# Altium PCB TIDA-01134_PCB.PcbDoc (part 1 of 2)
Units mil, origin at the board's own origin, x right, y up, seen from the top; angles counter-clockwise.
Board outline 4724.41 x 2283.46 mil, 2 copper layers (Top Layer, Bottom Layer), stack 62 mil thick; 90 components, 33 nets, 177 pads, 316 vias.
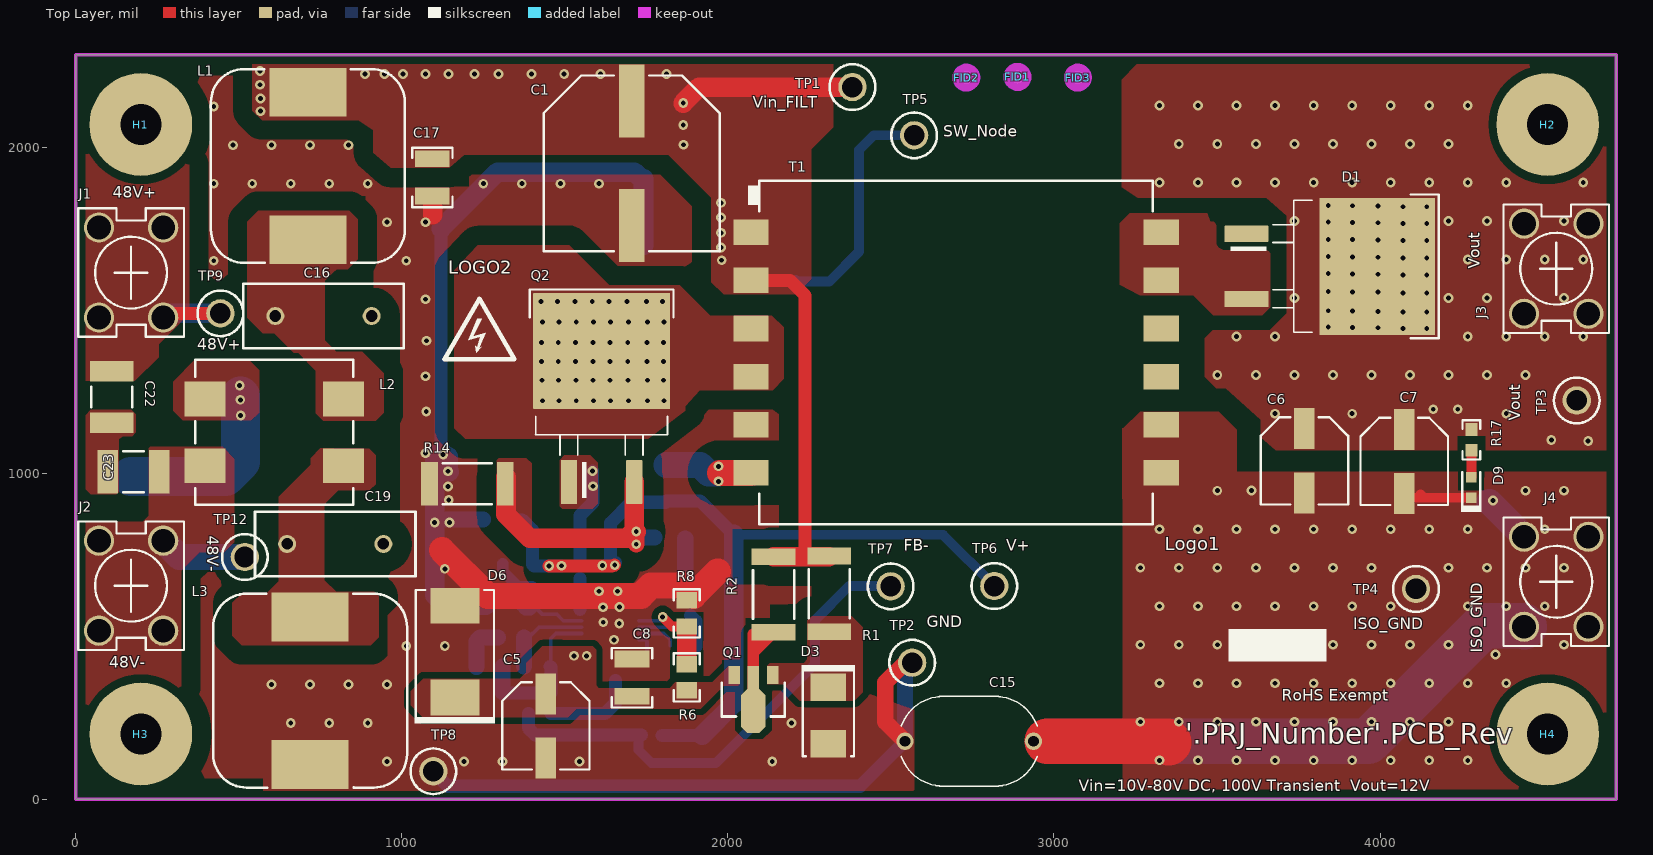
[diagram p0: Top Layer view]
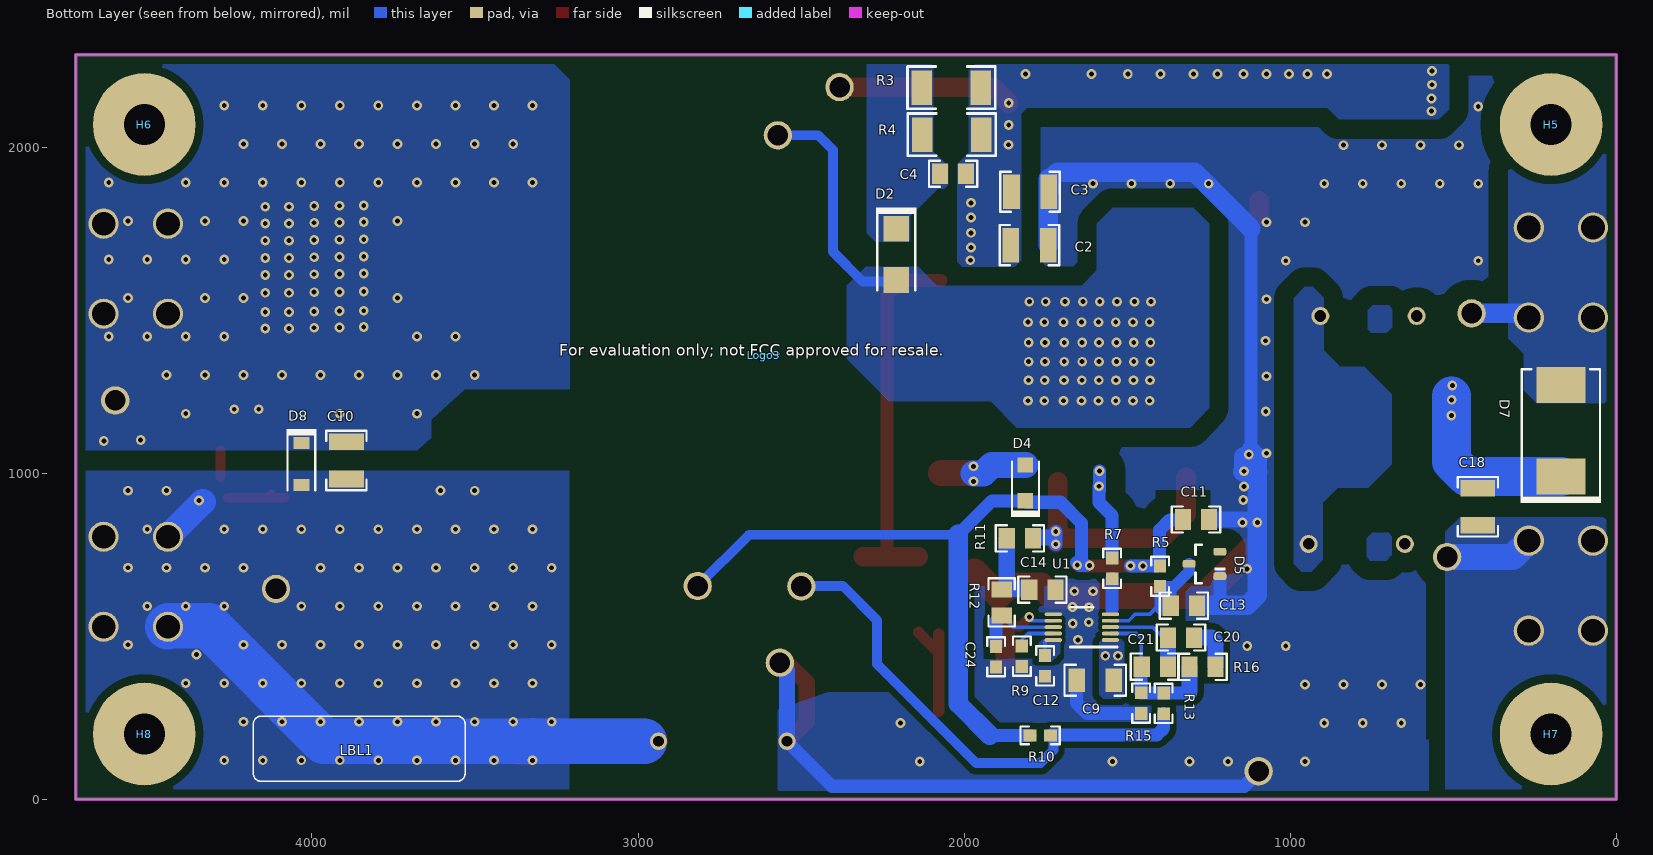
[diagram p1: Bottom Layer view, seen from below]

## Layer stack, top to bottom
Top Solder: solder mask 0.4, Solder Resist, Dk 3.5
Top Layer: signal copper 1.4
Dielectric1: core 59.2, FR-4, Dk 4.8
Bottom Layer: signal copper 1.4
Bottom Solder: solder mask 0.4, Solder Resist, Dk 3.5

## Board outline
0,0 4724.41,0 4724.41,2283.46 0,2283.46

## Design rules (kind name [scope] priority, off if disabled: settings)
AcuteAngle [All] p1: minimum=4.50000000000000E+0001 checktracksonly=FALSE
AssemblyTestPointUsage [All] p1: valid=2
BoardOutlineClearance BoardOutlineClearance_MountingHoles [OnCopper and InComponentClass('Mounting Holes')] p1: gap=21
BoardOutlineClearance BoardOutlineClearance_Poly [OnCopper and IsPoly] p2: gap=25
BoardOutlineClearance [OnCopper and Not InComponentClass('Logo') and not InComponentClass('FiducialMark') and not InRegion(1000,500,4000,800) and not InPoly] p3: gap=0
Clearance Clearance_PolyGND_LV [InNamedPolygon('BOTTOM_LAYER_GND_LV')or InNamedPolygon('TOP_LAYER_GND_LV')] p1: gap=20
Clearance Clearance_PolyGND_Big [InNamedPolygon('TOP_LAYER_GND_P064') Or InNamedPolygon ('BOTTOM_LAYER_GND_P066')or InNamedPolygon('BOTTOM_LAYER_GND_LV')] p2: gap=60
Clearance Clearance_Poly_U1 [InPolygon vs InNet('FB') OR InNet('COMP') OR InNet('VCC') OR InNet('OUT') OR InNet('CS') or InNet('UVLO') or InNet('RT/SYNC')or InNet('SS')] p3: gap=12
Clearance Clearance_Poly [InPolygon] p4: gap=25
Clearance Clearance_U1 [(InNet('VIN') OR InNet('FB') OR InNet('COMP') OR InNet('VCC') OR InNet('OUT') OR InNet('CS') or InNet('UVLO') or InNet('RT/SYNC')or InNet('SS'))or ( InNet('GND') ) vs (InNet('VIN') OR InNet('FB') OR InNet('COMP') OR InNet('VCC') OR InNet('OUT') OR InNet('CS') or InNet('UVLO') or InNet('RT/SYNC')or InNet('SS'))  or ( InNet('GND') and InComponent('U1'))] p5: gap=7.8
Clearance Clearance_Keepouts [((IsTrack Or IsArc) And Not InPoly) And IsFree and IsKeepOut vs ((IsTrack Or IsArc) And Not InPoly) And IsFree and IsKeepOut] p6: gap=0
Clearance [All] p7: gap=12
ComponentClearance ComponentClearance_MountingHoles_FiducialMarks [InComponentClass('Mounting Holes') vs InComponentClass('FiducialMark')] p1: gap=50 collisioncheckmode=3 verticalgap=10 showdistances=FALSE
ComponentClearance ComponentClearance_Shunt [InComponentClass('Header') vs InComponentClass('Shunt')] p2: gap=0 collisioncheckmode=3 verticalgap=0 showdistances=FALSE
ComponentClearance ComponentClearance_Logo [InComponentClass('Logo')] p3: gap=50 collisioncheckmode=3 verticalgap=10 showdistances=FALSE
ComponentClearance ComponentClearance_ScrewToNut [(HasFootprint('NY PMS 440 0025 PH')) vs (HasFootprint('Keystone_1902C'))] p4: gap=5 collisioncheckmode=3 verticalgap=10 showdistances=FALSE
ComponentClearance ComponentClearance_MountingHoles [InComponentClass('Mounting Holes')] p5: gap=78.74 collisioncheckmode=3 verticalgap=100000 showdistances=FALSE
ComponentClearance ComponentClearance_SmallPassives [HasFootprint('0201*') or HasFootprint('0402*') or HasFootprint('0508') or HasFootprint('0603*') or HasFootprint('0612') or HasFootprint('0805*') or HasFootprint('0815*') or HasFootprint('0830*') or HasFootprint('1206*') or HasFootprint('1210*') or HasFootprint('1808*') or HasFootprint('1812*') or HasFootprint('1825*') or HasFootprint('2010*') or HasFootprint('2220*') or HasFootprint('2225*') or HasFootprint('2512*') or HasFootprint('2728*') or HasFootprint('3518*') vs HasFootprint('0201*') or HasFootprint('0402*') or HasFootprint('0508') or HasFootprint('0603*') or HasFootprint('0612') or HasFootprint('0805*') or HasFootprint('0815*') or HasFootprint('0830*') or HasFootprint('1206*') or HasFootprint('1210*') or HasFootprint('1808*') or HasFootprint('1812*') or HasFootprint('1825*') or HasFootprint('2010*') or HasFootprint('2220*') or HasFootprint('2225*') or HasFootprint('2512*') or HasFootprint('2728*') or HasFootprint('3518*')] p6: gap=14.96 collisioncheckmode=3 verticalgap=10 showdistances=FALSE
ComponentClearance ComponentClearance_THtoSMT [IsThruComponent vs IsSMTComponent] p7: gap=20 collisioncheckmode=3 verticalgap=20 showdistances=FALSE
ComponentClearance ComponentClearance_THtoTH [IsThruComponent vs IsThruComponent] p8: gap=30 collisioncheckmode=3 verticalgap=20 showdistances=FALSE
ComponentClearance [All] p9: gap=30 collisioncheckmode=3 verticalgap=10 showdistances=FALSE
DiffPairsRouting [All] p1: maxlimit=100 minlimit=10 mostfreqgap=10 toplayer_minwidth=15 toplayer_maxwidth=15 toplayer_prefwidth=15 bottomlayer_minwidth=15 bottomlayer_maxwidth=15 bottomlayer_prefwidth=15 maxuncoupledlength=1000
FabricationTestPointUsage TestPointUsage [All] p1: valid=2 allowmultiple=FALSE
FabricationTestpoint Testpoint [All] p1: side=3 testpointundercomponent=TRUE minsize=40 maxsize=100 preferedsize=60 minholesize=0 maxholesize=40 preferedholesize=32 testpointgrid=1 allowsidetop=TRUE allowsidebottom=TRUE usegrid=TRUE gridtolerance=0.01
FanoutControl Fanout_LCC [IsLCC] p1: bgadir=Out bgaviamode=Centered fanoutstyle=Auto fanoutdirection=Alternating viagrid=1 // Fanout_LCC (Default Rule)
FanoutControl Fanout_BGA [IsBGA] p2: bgadir=Out bgaviamode=Centered fanoutstyle=Auto fanoutdirection=Alternating viagrid=1 // Fanout_BGA (Default Rule)
FanoutControl Fanout_Default [All] p4: bgadir=Out bgaviamode=Centered fanoutstyle=Auto fanoutdirection=Alternating viagrid=1 // Fanout_Default (Default Rule)
FanoutControl Fanout_Small [(CompPinCount < 5)] p5: bgadir=Out bgaviamode=Centered fanoutstyle=Auto fanoutdirection=OutThenIn viagrid=1 // Fanout_Small (Default Rule)
HoleSize [All] p1: absolutevalues=TRUE maxlimit=251 minlimit=7.87 maxpercent=80.000 minpercent=20.000
MinimumAnnularRing MinimumAnnularRing_ThermalPadVias [IsVia and InAnyComponent] p1: minimumring=5.91
MinimumAnnularRing [All] p2: minimumring=7
MinimumSolderMaskSliver MinimumSolderMaskSliver_Logo [InComponentClass('Logo') vs InComponentClass('Logo')] p1: minsoldermaskwidth=0.7
MinimumSolderMaskSliver [All] p2: minsoldermaskwidth=2
PlaneConnect [All] p1: planeconnectstyle=Direct reliefexpansion=10 reliefentries=4 reliefconductorwidth=10 reliefairgap=10
PolygonConnect [All] p1: connectstyle=Direct reliefconductorwidth=10 reliefentries=4 polygonreliefangle="90 Angle" airgapwidth=10
RoutingVias ThermalPadVias [IsVia and InAnyComponent] p1: holewidth=7.87 width=19.68 viastyle="Through Hole" minholewidth=7.87 minwidth=19.68 maxholewidth=12.99 maxwidth=23.62
RoutingVias [All] p2: holewidth=16 width=34 viastyle="Through Hole" minholewidth=7.87 minwidth=26 maxholewidth=40 maxwidth=65
SilkToBoardRegionClearance [Not ((IsComment or IsDesignator) And (Hide <> 'False')) and not InRegion(1000,500,4000,800)] p1:
SilkToSilkClearance SilkToSilkClearance_Pb-FreeLogo [(HasFootprint('Pb-Free_Overlay_Medium') OR HasFootprint('Pb-Free_Overlay_Small')) vs (HasFootprint('Pb-Free_Overlay_Medium') OR HasFootprint('Pb-Free_Overlay_Small'))] p1: silktosilkclearance=0
SilkToSilkClearance [All] p2: silktosilkclearance=4
SilkToSolderMaskClearance SilkToComponentPadClearance [IsPad and InAnycomponent] p1: minsilkscreentomaskgap=0 clearancetoexposedcopper=TRUE
SilkToSolderMaskClearance "Silk to Solder Mask Opening" [All] p2: minsilkscreentomaskgap=0 clearancetoexposedcopper=FALSE
SolderMaskExpansion [All] p1: expansion=2
Width [All] p1: maxlimit=400 minlimit=6 preferedwidth=10 checkconnectedcopper=TRUE
15 further rules are at their usual default settings.

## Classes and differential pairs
component class Label: LBL1
component class AssemblyNote: ZZ1 ZZ2 ZZ3 ZZ4
component class FiducialMark: FID1 FID2 FID3
component class TIDA-01134_Hardware: FID1 FID2 FID3 H1 H2 H3 H4 H5 H6 H7 H8 LBL1 Logo1 LOGO2 Logo3 ZZ1 ZZ2 ZZ3 ZZ4
component class "Mounting Holes": H1 H2 H3 H4
component class TIDA-01134_FlyBack_Converter: C1 C2 C3 C4 C5 C6 C7 C8 C9 C10 C11 C12 C13 C14 C15 C20 C21 C24 D1 D2 D3 D4 D5 D6 D8 D9 J3 J4 Q1 Q2 R1 R2 R3 R4 R5 R6 R7 R8 R9 R10 R11 R12 R13 R14 R15 R16 R17 T1 TP2 TP3 TP4 TP5 TP6 TP7 TP8 U1
component class TIDA-01134_Protection_EMI_Filter: C16 C17 C18 C19 C22 C23 D7 J1 J2 L1 L2 L3 TP1 TP9 TP12

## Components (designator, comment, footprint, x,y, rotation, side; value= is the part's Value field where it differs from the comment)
C1 "EEV-FK2A470Q" SM_RADIAL_H13 1705,1950 r270 top
C2 "GRM32DC72A475KE01L" 1210_220 1799.57,1699 r180 bottom
C3 "GRM32DC72A475KE01L" 1210_220 1797.89,1863 r180 bottom
C4 "CGA4J2X7R2A104K125AA" 0805_HV 2034,1918 r0 bottom
C5 "EEE-FK1K4R7P" SM_RADIAL_D 1442,225 r270 top
C6 "EEE-FK1E101XP" SM_RADIAL_D8 3768,1038 r270 top
C7 "EEE-FK1E101XP" SM_RADIAL_D8 4074,1036 r270 top
C8 "GRM32DC72A475KE01L" 1210_220 1706,373 r90 top
C9 "GRM319R72A104KA01D" 1206 1598,365 r0 bottom
C10 "GRM32ER71E226KE15L" 1210_270 3894,1039 r270 bottom
C11 "GRM216R61E105KA12D" 0805_HV 1289,858 r180 bottom
C12 "GRM188R71H104KA93D" 0603 1752,409 r270 bottom
C13 "GRM216R61E105KA12D" 0805_HV 1326,594 r180 bottom
C14 "GCM2165C1H102JA16D" 0805_HV 1760,643 r180 bottom
C15 "DE1E3KX222MA4BL01" CAPRD1000W60D900H1200 2740,178 r180 top
C16 "VY2472M49Y5US63V7" VY2_1250x500x1650 760,1482 r0 top
C17 "GRM32DC72A475KE01L" 1210_220 1094,1907 r270 top
C18 "GRM32DC72A475KE01L" 1210_220 425,897 r270 bottom
C19 "VY2472M49Y5US63V7" VY2_1250x500x1650 796,783 r180 top
C20 "GRM219R71H333KA01D" 0805_HV 1335,496 r180 bottom
C21 "GRM2165C1H821JA01D" 0805_HV 1415,407 r0 bottom
C22 "VJ1812Y103KXEAT5Z" 1812 111,1234 r270 top
C23 "VJ1812Y103KXEAT5Z" 1812 177,1004 r0 top
C24 "GRM1885C1H100JA01D" 0603 1902,437 r270 bottom
D1 "STPS8H100G-TR" DDPAK 3836,1634 r0 top
D2 "STPS1150A" SMA 2208,1671 r270 bottom
D3 "1SMB5942BT3G" SMB 2308,257 r270 top
D4 "PMEG10010ELRX" SOD-123W 1812,970 r90 bottom
D5 "MMBZ5244BLT1G" SOT-23 1263,722 r0 bottom
D6 "SMCJ54A" SMC 1163,453 r90 top
D7 "B3100-13-F" SMC 170,1130 r90 bottom
D8 "MMSZ5246B-7-F" SOD-123 4031.95,1028 r270 bottom
D9 "150060GS75000" WL-SMCW_GREEN 4279.22,956 r90 top
FID1 "Fiducial" Fiducial10-20 2888,2215 r0 top
FID2 "Fiducial" Fiducial10-20 2731,2213 r0 top
FID3 "Fiducial" Fiducial10-20 3073,2213 r0 top
H1 "NY PMS 440 0025 PH" "NY PMS 440 0025 PH" 200,2068.9 r0 top locked
H2 "NY PMS 440 0025 PH" "NY PMS 440 0025 PH" 4513.78,2068.9 r0 top locked
H3 "NY PMS 440 0025 PH" "NY PMS 440 0025 PH" 200,200 r0 top locked
H4 "NY PMS 440 0025 PH" "NY PMS 440 0025 PH" 4513.78,200 r0 top locked
H5 "1902C" Keystone_1902C 200,2068.9 r180 bottom locked
H6 "1902C" Keystone_1902C 4513.78,2068.9 r180 bottom locked
H7 "1902C" Keystone_1902C 200,200 r180 bottom locked
H8 "1902C" Keystone_1902C 4513.78,200 r180 bottom locked
J1 "7693" 7693 170,1615 r0 top
J2 "7693" 7693 170,655 r0 top
J3 "7693" 7693 4540,1627 r0 top
J4 "7693" 7693 4540,667 r0 top
L1 "MSS1583-154KEB" MSS1583 712,1942 r90 top
L2 "ACM1211-102-2PL-TL01" TDK_ACM1211 609,1125 r90 top
L3 "MSS1583-154KEB" MSS1583 719,333 r270 top
LBL1 "Size: 0.65\" x 0.20 \"" Label_650x200 3855,155 r180 bottom
Logo1 "EU RoHS Exempt Logo" EURoHS_Exempt_60mil 3868,310 r0 top
LOGO2 "DANGER HIGH VOLTAGE" IEC_HighVoltage_Small 1238,1438 r0 top
Logo3 "FCC disclaimer" FCC_disclaimer 2614,1361 r180 bottom
Q1 "ZXTN4004ZTA" SOT-89-3 2078,306 r270 top
Q2 "IRFS4227PBF" DDPAK 1613,1219 r90 top
R1 "CRCW251220K0FKEG" 2512 2311,630 r90 top
R2 "CRCW251220R0FKEG" 2512 2140,628 r90 top
R3 "CRCW20105K10JNEF" 2010 2039,2182 r180 bottom
R4 "CRCW20105K10JNEF" 2010 2038,2038 r180 bottom
R5 "CRCW060310R0FKEA" 0603 1399,684 r90 bottom
R6 "CRCW0805100KFKEA" 0805_HV 1874,374 r270 top
R7 "CRCW06034R70JNEA" 0603 1546,708 r90 bottom
R8 "CRCW080514K3FKEA" 0805_HV 1874,570 r270 top
R9 "CRCW060347K5FKEA" 0603 1823,439 r90 bottom
R10 "CRCW060349R9FKEA" 0603 1767,196 r0 bottom
R11 "CRCW0805100RFKEA" 0805_HV 1829,800 r0 bottom
R12 "CRCW08052K49FKEA" 0805_HV 1885,603.59 r270 bottom
R13 "CRCW060351K1FKEA" 0603 1388,294 r270 bottom
R14 "CRM2512-FX-R100ELF" 2512 1201,968 r0 top
R15 "CRCW06035K36FKEA" 0603 1457,295 r90 bottom
R16 "CRCW080591K0JNEA" 0805_HV 1269,406 r180 bottom
R17 "CRCW060310K0FKEA" 0603 4279.95,1102 r90 top
T1 "UA8263-AL" Coilcraft_UA8263-AL 2700,1370 r0 top
TP1 "5005" Keystone5005 2382,2184 r0 top
TP2 "5006" Keystone5006 2565,419 r0 top
TP3 "5005" Keystone5005 4603,1223 r0 top
TP4 "5006" Keystone5006 4110,645 r0 top
TP5 "5005" Keystone5005 2571,2036 r0 top
TP6 "5005" Keystone5005 2817,654 r0 top
TP7 "5122" Keystone5122 2499,653 r0 top
TP8 "5006" Keystone5006 1097,86 r0 top
TP9 "5005" Keystone5005 444,1490 r0 top
TP12 "5006" Keystone5006 519,743 r0 top
U1 "LM5022QDGSRQ1" DGS0010A_N 1639,528 r0 bottom
ZZ1 "This Assembly Note is for PCB labels only" AssemblyNoteLabel 185,3938 r0 top
ZZ2 "This Assembly Note will show in the PcbDoc and associated outputs" AssemblyNote 185,3829.11 r0 top
ZZ3 "This Assembly Note will show in the PcbDoc and associated outputs" AssemblyNote 185,3740.56 r0 top
ZZ4 "This Assembly Note will show in the PcbDoc and associated outputs" AssemblyNote 185,3652 r0 top

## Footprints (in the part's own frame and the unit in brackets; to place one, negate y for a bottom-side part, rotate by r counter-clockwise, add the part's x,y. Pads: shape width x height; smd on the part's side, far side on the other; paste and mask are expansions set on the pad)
0603 [mm] "0603 from SM-752 data"
  rect 1x0.95 smd: 1(-0.8,0) 2(0.8,0)
  silkscreen extent -1.52,-0.69 1.52,0.69, body extent -0.87,-0.47 0.87,0.47, height 1
0805_HV [mil] "0805 with 30mil clearance between pads"
  rect 50x63 smd: 1(-40,0) 2(40,0)
  silkscreen extent -74,-40 74,40, body extent -43,-29 43,29, height 57
1206 [mm] "1206 from SM-752 data"
  rect 1.3x1.85 smd: 1(-1.45,0) 2(1.45,0)
  silkscreen extent -2.4,-1.21 2.4,1.21, body extent -1.7,-0.9 1.7,0.9, height 1.35
1210_220 [mm] "1210"
  rect 1.3x2.7 smd: 1(-1.45,0) 2(1.45,0)
  silkscreen extent -2.32,-1.57 2.32,1.57, body extent -1.7,-1.35 1.7,1.35, height 2.2
1210_270 [mm] "1210"
  rect 1.3x2.7 smd: 1(-1.45,0) 2(1.45,0)
  silkscreen extent -2.32,-1.57 2.32,1.57, body extent -1.7,-1.35 1.7,1.35, height 2.7
1812 [mm]
  rect 1.6x3.4 smd: 1(-2,0) 2(2,0)
  silkscreen extent -0.8,-1.6 0.8,1.6, body extent -2.4,-1.7 2.4,1.7, height 1.35
2010 [mm] "Chip Capacitor, Body 5.08x2.54mm, IPC Medium Density"
  rect 1.6x2.7 smd: 1(-2.3,0) 2(2.3,0)
  silkscreen extent -3.42,-1.65 3.42,1.65, body extent -2.73,-1.45 2.73,1.45, height 1.66
2512 [mm] "Chip Resistor, Body 6.3x3.2mm, IPC Medium Density"
  rect 1.3x3.4 smd: 1(-2.95,0) 2(2.95,0)
  silkscreen extent -1.9,-1.6 1.9,1.6, body extent -3.22,-1.67 3.22,1.67, height 0.71
7693 [mm] "Keystone Electronics 7693 recommended land pattern"
  round 2.35 hole 1.85: 1(-2.502,3.505) 2(2.502,3.505) 3(-2.502,-3.505) 4(2.502,-3.505)
  silkscreen extent -4.11,-5 4.11,5, body extent -3.95,-3.94 3.95,3.96, height 8.86
AssemblyNote [mil] "Assembly Note"
AssemblyNoteLabel [mil] "Assembly Note for PCB Labels"
CAPRD1000W60D900H1200 [mm] "Disk, Radial Capacitor"
  round 1.35 hole 0.85: 1(-5,0) 2(5,0)
  silkscreen extent -5.3,-3.5 5.3,3.5, body extent -4.48,-3.5 4.48,3.5, height 11.99
Coilcraft_UA8263-AL [mm] "SMD, 12-Leads, Body 34.29x26.75mm, Pitch 3.75mm"
  rect 2.75x2 smd: 1(-15.975,9.375) 2(-15.975,5.625) 3(-15.975,1.875) 4(-15.975,-1.875) 5(-15.975,-5.625) 6(-15.975,-9.375) 7(15.975,-9.375) 8(15.975,-5.625) 9(15.975,-1.875) 10(15.975,1.875) 11(15.975,5.625) 12(15.975,9.375)
  silkscreen extent -16.2,-13.38 15.32,13.37, body extent -17.14,-13.37 17.15,13.38, height 13.6
DDPAK [mil] "D2-PAK, 3-Pads, Body 9.7x10.4mm (max), TO-263AB, using Vishay Silionix recommended pad sizes"
  rrect8% 135x49.49 smd: 1(-246.06,100) 3(-246.06,-100)
  rrect1% 355x420 smd paste-181.1: 4(155.51,0)
  silkscreen extent -295,-220 344,220, body extent -295,-202 324,202, height 180
DGS0010A_N [mm] "TSSOP, 10-Leads, Body 3x3mm, Pitch 0.5mm, IPC Medium Density"
  oval 1.35x0.3 smd: 1(-2.225,1) 2(-2.225,0.5) 3(-2.225,0) 4(-2.225,-0.5) 5(-2.225,-1) 6(2.225,-1) 7(2.225,-0.5) 8(2.225,0) 9(2.225,0.5) 10(2.225,1)
  silkscreen extent -2.75,-1.55 0.9,1.55, body extent -2.45,-1.5 2.45,1.5, height 0.96
EURoHS_Exempt_60mil [mil] "EU RoHS Exempt symbol"
FCC_disclaimer [mil]
Fiducial10-20 [mm]
  round 1 smd mask+0.5: 1(0,0)
  Top Layer keep-out circle w1.178: c0,0 r0.5
IEC_HighVoltage_Small [mil]
  silkscreen extent -107,-88 107,97
Keystone5005 [mil] "Keystone Compact loops"
  round 87 hole 63: 1(0,0)
  silkscreen extent -70,-70 70,70, body extent -63,-63 62,63, height 225
Keystone5006 [mil] "Keystone Compact loops"
  round 87 hole 63: 1(0,0)
  silkscreen extent -70,-70 70,70, body extent -63,-63 62,63, height 225
Keystone5122 [mil] "Keystone Compact loops"
  round 87 hole 63: 1(0,0)
  silkscreen extent -70,-70 70,70, body extent -63,-63 62,63, height 225
Keystone_1902C [mil] "Hex Standoff, 4-40 threaded, nylon"
  round 1 on Mech4: 0(0,0)
  body extent -145,-126 146,126, height 501
Label_650x200 [mil] "Thermal Transfer Label"
  round 1 on Mech14: 0(0,0)
  silkscreen extent -325,-100 325,100, body extent -325,-100 325,100, height 1
MSS1583 [mm] "Coilcraft recommended land pattern"
  rect 3.8x6 smd: 1(-5.75,0) 2(5.75,0)
  silkscreen extent -7.55,-7.55 7.55,7.55, body extent -7.55,-7.55 7.55,7.55, height 9.05
"NY PMS 440 0025 PH" [mm] "4-40 nylon screw and mounting hole"
  round 8 hole 3.2: 1(0,0)
  body extent -3.3,-3.3 3.3,3.3, height 2.69
SM_RADIAL_D [mm] "6.3 x 5.8mm:  Panasonic D"
  rect 3.2x1.6 smd: 1(-2.5,0) 2(2.5,0)
  silkscreen extent -3.4,-3.4 3.4,3.4, body extent -3.4,-3.4 3.4,3.4, height 6.1
SM_RADIAL_D8 [mm] "6.3 x 7.7mm:  Panasonic D8"
  rect 3.2x1.6 smd: 1(-2.5,0) 2(2.5,0)
  silkscreen extent -3.4,-3.4 3.4,3.4, body extent -3.4,-3.4 3.4,3.4, height 8.01
SM_RADIAL_H13 [mm] "12.5 x 13.5mm:  Panasonic H13"
  rect 5.7x2 smd: 1(-4.85,0) 2(4.85,0)
  silkscreen extent -6.85,-6.85 6.85,6.85, body extent -6.85,-6.85 6.85,6.85, height 14
SMA [mm] "Molded Diode, 2-Leads, Body 4.3x2.6mm, IPC Medium Density, based on OnSemi component dimensions and land pattern"
  rect 2x2 smd: 1(-2,0) 2(2,0)
  silkscreen extent -3.66,-1.57 2.79,1.57, body extent -2.6,-1.3 2.6,1.3, height 2.42
SMB [mil] "Molded Diode, 2-Leads, Body 5.4x3.6mm, IPC Medium Density, based on OnSemi component dimensions"
  rect 85x107.99 smd: 1(-87.01,0) 2(87.01,0)
  silkscreen extent -155,-82 125,82, body extent -106,-71 106,71, height 91
SMC [mil] "Molded Diode, 2-Leads, Body 6.9x5.8mm, IPC Medium Density, based on OnSemi component dimensions and land patterns"
  rect 110x150 smd: 1(-140.49,0) 2(140.49,0)
  silkscreen extent -221,-124 189,123, body extent -156,-116 156,116, height 91
SOD-123 [mm] "On Semi recommended land pattern"
  rect 0.915x1.22 smd: 1(-1.637,0) 2(1.637,0)
  silkscreen extent -2.74,-1.17 2.03,1.17, body extent -1.93,-0.9 1.93,0.9, height 1.35
SOD-123W [mm] "NXP recommended land pattern"
  rect 1.2x1.2 smd paste-0.05: 1(-1.4,0) 2(1.4,0)
  silkscreen extent -2.64,-1.14 1.68,1.14, body extent -1.85,-0.95 1.85,0.95, height 1.1
SOT-23 [mm] "SOT23, 3-Leads, Body 2.9x1.3mm, Pitch 0.95mm, Lead Span 2.5mm, IPC Medium Density"
  rrect50% 1x0.6 smd: 1(-1.2,0.95) 2(-1.2,-0.95) 3(1.2,0)
  silkscreen extent -1.62,-1.5 0.7,1.5, body extent -1.16,-1.45 1.21,1.45, height 1
SOT-89-3 [mm] "SOT, 3-Leads, Body 4.6 x 2.6 mm, Pitch 1.5mm"
  rect 1.4x0.9 smd: 1(-1.9,1.5) 3(-1.9,-1.5)
  rect 1.8x0.9 smd: 2(-1.7,0)
  oct 3.4x1.9 smd: 4(0.9,0)
  silkscreen extent -1.3,-2.45 1.33,2.45, body extent -2.42,-2.28 1.83,2.32, height 1.62
TDK_ACM1211 [mm] "SMT, 4-Leads, Body 12x11mm"
  rect 2.7x3.2 smd: 1(-2.6,5.4) 2(2.6,5.4) 3(2.6,-5.4) 4(-2.6,-5.4)
  silkscreen extent -5.65,-6.15 5.65,6.15, body extent -5.65,-6.15 5.65,6.15, height 6
VY2_1250x500x1650 [mm] "TH, 2- Leads, Body 12.5x5mm, Pin Spacing 7.5mm"
  round 1.4 hole 0.9: 1(-3.75,0) 2(3.75,0)
  silkscreen extent -6.25,-2.5 6.25,2.5, body extent -6.2,-2.5 6.25,2.5, height 16.49
WL-SMCW_GREEN [mm] "WURTH"
  rect 0.8x0.8 smd: 1(-0.8,0) 2(0.8,0)
  silkscreen extent -1.9,-0.8 1.2,0.8, body extent -0.85,-0.45 0.85,0.45, height 0.8

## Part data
C1: "CAP, AL, 47 μF, 100 V, +/- 20%, 0.32 ohm, AEC-Q200 Grade 2, SMD"
C2 C3 C8 C17 C18: "CAP, CERM, 4.7 μF, 100 V, +/- 10%, X7S, 1210"
C4: "CAP, CERM, 0.1 μF, 100 V, +/- 10%, X7R, AEC-Q200 Grade 1, 0805"
C5: "CAP, AL, 4.7 μF, 80 V, +/- 20%, 3 ohm, AEC-Q200 Grade 2, SMD"
C6 C7: "CAP, AL, 100 μF, 25 V, +/- 20%, 0.34 ohm, AEC-Q200 Grade 2, SMD"
C9: "CAP, CERM, 0.1 μF, 100 V, +/- 10%, X7R, 1206"
C10: "CAP, CERM, 22 μF, 25 V, +/- 10%, X7R, 1210"
C11 C13: "CAP, CERM, 1 μF, 25 V, +/- 10%, X5R, 0805"
C12: "CAP, CERM, 0.1 μF, 50 V, +/- 10%, X7R, 0603"
C14: "CAP, CERM, 1000 pF, 50 V, +/- 5%, C0G/NP0, AEC-Q200 Grade 1, 0805"
C15: "CAP, CERM, 2200 pF, 250 V, +/- 20%, E, Cap, 7x12x9 mm"
C16 C19: "CAP, CERM, 4700 pF, 440 V, +/- 20%, Y5U, TH, 12.5x5mm"
C20: "CAP, CERM, 0.033 μF, 50 V, +/- 10%, X7R, 0805"
C21: "CAP, CERM, 820 pF, 50 V, +/- 5%, C0G/NP0, 0805"
C22 C23: "CAP, CERM, 0.01 μF, 500 V, +/- 10%, X7R, 1812"
C24: "CAP, CERM, 10 pF, 50 V, +/- 5%, C0G/NP0, 0603"
D1: "Diode, Schottky, 100 V, 8 A, DDPAK"
D2: "Diode, Schottky, 150 V, 1 A, SMA"
D3: "Diode, Zener, 51 V, 550 mW, SMB"
D4: "Diode, Schottky, 100 V, 1 A, AEC-Q101, SOD-123W"
D5: "Diode, Zener, 14 V, 225 mW, SOT-23"
D6: "Diode, TVS, Uni, 54 V, SMC"
D7: "Diode, Schottky, 100 V, 3 A, SMC"
D8: "Diode, Zener, 16 V, 500 mW, SOD-123"
D9: "LED, Green, SMD"
FID1 FID2 FID3: "Fiducial mark.  There is nothing to buy or mount."
H1 H2 H3 H4: "Machine Screw, Round, #4-40 x 1/4, Nylon, Philips panhead"
H5 H6 H7 H8: "Standoff, Hex, 0.5\"L #4-40 Nylon"
J1 J2 J3 J4: "Terminal screw, vertical, snap-in"
L1 L3: "Inductor, Drum Core, Ferrite, 150 μH, 2.2 A, 0.138 ohm, SMD"
L2: "Coupled inductor, 6 A, 0.014 ohm, SMD"
LBL1: library part THT-14-423-10, "Thermal Transfer Printable Labels, 0.650\" W x 0.200\" H - 10,000 per roll"
Logo1: library part EURoHS_Exempt
LOGO2: library part IEC_HighVoltage, "IEC 61010-1 High Voltage Warning"
Logo3: library part FCC_disclaimer, "FCC_disclaimer"
Q1: library part "ZXTN4004ZTA, Diodes Inc.", "Transistor, NPN, 150 V, 1 A, SOT-89"
Q2: "MOSFET, N-CH, 200 V, 62 A, DDPAK"
R1: "RES, 20.0 k, 1%, 1 W, AEC-Q200 Grade 0, 2512"
R2: "RES, 20.0, 1%, 1 W, AEC-Q200 Grade 0, 2512"
R3 R4: "RES, 5.1 k, 5%, 0.75 W, AEC-Q200 Grade 0, 2010"
R5: "RES, 10.0, 1%, 0.1 W, 0603"
R6: "RES, 100 k, 1%, 0.125 W, 0805"
R7: "RES, 4.7, 5%, 0.1 W, 0603"
R8: "RES, 14.3 k, 1%, 0.125 W, 0805"
R9: "RES, 47.5 k, 1%, 0.1 W, 0603"
R10: "RES, 49.9, 1%, 0.1 W, 0603"
R11: "RES, 100, 1%, 0.125 W, 0805"
R12: "RES, 2.49 k, 1%, 0.125 W, 0805"
R13: "RES, 51.1 k, 1%, 0.1 W, 0603"
R14: "RES, 0.1, 1%, 2 W, 2512"
R15: "RES, 5.36 k, 1%, 0.1 W, 0603"
R16: "RES, 91 k, 5%, 0.125 W, 0805"
R17: "RES, 10.0 k, 1%, 0.1 W, 0603"
T1: "Transformer, Flyback, EFD25, 35 uH, SMT"
TP1 TP3 TP5 TP6 TP9: "Test Point, Compact, Red, TH"
TP2 TP4 TP8 TP12: "Test Point, Compact, Black, TH"
TP7: "Test Point, Compact, Blue, TH"
U1: "2.2MHz 60-V Low Side Controller for Boost, SEPIC and Flyback, DGS0010A (VSSOP-10)"
ZZ1: library part AssemblyNoteLabel
ZZ2 ZZ3 ZZ4: library part AssemblyNote

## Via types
v1: diameter 30, hole 15, Top Layer to Bottom Layer, 316 vias

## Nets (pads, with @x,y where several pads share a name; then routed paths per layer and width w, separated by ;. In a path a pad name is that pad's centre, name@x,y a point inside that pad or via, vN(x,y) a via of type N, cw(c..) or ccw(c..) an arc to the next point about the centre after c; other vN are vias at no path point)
48V+: C22.1 D7.2 J1.1 J1.2 J1.3 J1.4 TP9.1 | length 361.8
  Top Layer w40: J1.4@268.5,1477 281.5,1490 TP9.1@444,1490
  Bottom Layer w60: J1.4@268.5,1477 281.5,1490 TP9.1@444,1490
48V-: C18.2 C23.2 J2.1 J2.2 J2.3 J2.4 L2.1 TP12.1 | length 271.2
  Bottom Layer w80: J2.2@268.5,793 318.5,743 TP12.1@519,743
COMP: C20.1 C21.1 U1.3 | length 263.7
  Bottom Layer w11: C20.1@1388.76,496 1420.76,528 U1.3@1551.4,528
  Bottom Layer w50: C21.1@1375,408.24 C20.1@1375,496
CS: C24.1 R12.2 U1.8 | length 275.3
  Bottom Layer w11: U1.8@1726.6,528 1849.41,528 R12.2@1885,563.59
  Bottom Layer w40: R12.2@1885,563.59 1902,546.59 C24.1@1902,468.5
CS_RS: Q2.3 R11.1 R14.2 | length 848.2
  Top Layer w50: v1(1719,782) v1(1719,821)
  Top Layer w60: R14.2@1319.55,988 1319.55,873.45 1392,801 1690,801 1710,821 v1(1719,821) 1713,827 Q2.3@1713,972.94
  Bottom Layer w40: v1(1719,782) v1(1719,821) 1737,803
  Bottom Layer w50: 1737,803 R11.1@1775,803
EARTH: C16.2 C19.1
FB: C21.2 R13.1 R15.2 R16.1 U1.2 | length 495.5
  Bottom Layer w11: C21.2@1457,405 1457,493 1472.31,508.31 U1.2@1551.4,508.31
  Bottom Layer w40: 1309,330 1312.5,326.5 R15.2@1457,326.5 1457,405 C21.2@1455,407
  Bottom Layer w50: 1309,330 R16.1@1309,406
GND: C1.2 C2.2 C3.2 C5.2 C8.2 C9.2 C11.2 C12.2 C13.2 C14.2 C15.2 C17.2 C24.2 D3.2 D5.1 D6.2 L3.2 R8.1 R9.1 R14.1 R15.1 T1.5 TP2.1 TP8.1 U1.6 | length 6034.9
  Top Layer w50: C15.2@2543.15,178 2483,238.15 2483,358 2544,419 TP2.1@2565,419
  Top Layer w60: 1095,1793 C17.2@1095,1835.91
  Top Layer w80: 1123,764 1263,624 1733,624 1764,655 1863,655 1894,624 1969,699
  Bottom Layer w40: TP8.1@1097,86 1097,84 1141,40 2405.15,40 C15.2@2543.15,178 ; v1@1121,1068 1121,1750 ; 1214,595 1215.76,596.76 D5.1@1215.76,684.6 ; R15.1@1457,263.5 1623.5,263.5 1656,296 1656,364.09 C9.2@1655.09,365
  Bottom Layer w50: v1(1101,849) 1110,858 C11.2@1249,858 ; C15.2@2543.15,178 2543.15,397.15 TP2.1@2565,419
  Bottom Layer w60: v1@1121,1068 1103,1050 ; 1121,1750 1294,1923 1713,1923 1740.8,1895.2 C3.2@1740.8,1863 ; v1@1142,1007 1142,1029 ; v1@1145,1004 1101,1004 ; 1258,595 1214,595 1132,595 1101,626 v1(1101,849) 1101,1004 ; C3.2@1742,1902 1742,1698.51 C2.2@1742.49,1699 ; 1101,1004 1101,1005 ; 1101,1004 1100,1004 1101,1005 ; 1101,1005 1101,1048 1102,1049 ; 1102,1049 1101,1050 1103,1050 ; 1102,1049 1122,1029 1142,1029 ; 1102,1049 1103,1050 ; 1103,1050 1142,1050 1142,1029
  other v1: 954.89,116.12 1191.11,116.12 1309.22,116.12 1545.44,116.12 2135.99,116.12 659.61,234.23 777.72,234.23 895.83,234.23 2195.05,234.23 600.56,352.34 718.67,352.34 836.78,352.34 954.89,352.34 1013.94,470.45 1132.06,470.45 1651,489 1667,539 1618,543 1617,589 1668,590 1605,638 1662,638 1132.06,706.67 1146,849 1144,918 1142,959 1142,1006 1127,1057 1073,1061 1075,1189 1073,1297.22 1076,1406 1073,1533.44 423.39,1651.55 1013.94,1651.55 954.89,1769.66 1073,1769.66 423.39,1887.77 541.5,1887.77 659.61,1887.77 777.72,1887.77 895.83,1887.77 1250.17,1887.77 1368.28,1887.77 1486.39,1887.77 1604.5,1887.77 482.45,2005.88 600.56,2005.88 718.67,2005.88 836.78,2005.88 423.39,2123.99
ISO_GND: C6.2 C7.2 C10.2 C15.1 D8.2 D9.1 J4.1 J4.2 J4.3 J4.4 T1.7 T1.8 TP4.1 | length 2325.2
  Top Layer w30: C7.2@4084.02,924.5 4259.22,924.5 ; 4123.95,934.57 4134.02,924.5
  Top Layer w140: 2979,178 3348,178 3352,174
  Bottom Layer w80: v1@4334.5,912 J4.1@4441.5,805
  Bottom Layer w140: 2981,178 3322,178 ; 3323,179 3322,178 ; J4.3@4441.5,529 4438.5,532 4317,532 3963,178 3322,178
  other v1: 3323.75,119.54 3441.86,119.54 3559.97,119.54 3678.08,119.54 3796.19,119.54 3914.3,119.54 4032.41,119.54 4150.52,119.54 4268.63,119.54 3264.69,237.65 3382.8,237.65 3500.91,237.65 3619.02,237.65 3737.13,237.65 3855.24,237.65 3973.35,237.65 4091.46,237.65 4209.57,237.65 3323.75,355.76 3441.86,355.76 3559.97,355.76 3678.08,355.76 3796.19,355.76 3914.3,355.76 4032.41,355.76 4150.52,355.76 4268.63,355.76 4386.74,355.76 4354,444 3264.69,473.87 3382.8,473.87 3500.91,473.87 3619.02,473.87 3737.13,473.87 3855.24,473.87 3973.35,473.87 4091.46,473.87 4209.57,473.87 4563.9,473.87 3323.75,591.98 3441.86,591.98 3559.97,591.98 3678.08,591.98 3796.19,591.98 3914.3,591.98 4032.41,591.98 4268.63,591.98 4386.74,591.98 4504.85,591.98 3264.69,710.09 3382.8,710.09 3500.91,710.09 3619.02,710.09 3737.13,710.09 3855.24,710.09 3973.35,710.09 4209.57,710.09 4327.68,710.09 4445.79,710.09 4563.9,710.09 3323.75,828.2 3441.86,828.2 3559.97,828.2 3678.08,828.2 3796.19,828.2 3914.3,828.2 4032.41,828.2 4150.52,828.2 4268.63,828.2 4504.85,828.2 4346,916 3500.91,946.31 4445.79,946.31 4563.9,946.31 3606,947
NetC4_2: C4.2 D2.1 R3.1 R4.1
NetC11_1: C11.1 D4.1 R5.2 R10.2 TP6.1 | length 2741.9
  Top Layer w40: v1(1452,715) 1643,715 v1(1653,718)
  Bottom Layer w30: 2018,812 2019,811 2660,811 TP6.1@2817,654
  Bottom Layer w40: C11.1@1329,858 1330,857 1369,857 1401,825 1401,720.5 1405.5,716 v1(1490,716) ; v1@1656,726 1645,717 1627,717 1640,730 1640,847 1703.88,910.88 1808,910.88 D4.1@1812,914.88 1915.12,914.88 2018,812 ; R10.2@1798.5,196 1921,196
  Bottom Layer w60: 1921,196 2018,293 2018,812
  other v1: 1615,717
NetC14_1: C14.1 R11.2 R12.1 | length 202.7
  Bottom Layer w50: C14.1@1809,646 1870.41,646 R12.1@1871,646.59 ; R12.1@1869,659.59 R11.2@1869,800
NetC16_1: C16.1 L1.1 L2.3
NetC18_1: C18.1 D7.1 L2.2 | length 555.9
  Bottom Layer w120: D7.1@170,989.51 459.51,989.51 506,1036 v1(506,1177) v1@506,1236.6
  other v1: 505,1225 503,1269
NetC19_2: C19.2 L2.4 L3.1
NetC20_2: C20.2 R16.2 | length 149
  Bottom Layer w50: R16.2@1229,406 1229,484 1241,496 C20.2@1295,496
NetC22_2: C22.2 C23.1
NetD1_3: D1.3 T1.11 T1.12
NetD3_1: D3.1 Q1.1 R1.1
NetD4_2: D4.2 T1.6 | length 265.3
  Top Layer w80: 1976,1000 1976.91,1000.91 T1.6@2071.06,1000.91
  Bottom Layer w80: D4.2@1812,1025.12 1914.88,1025.12 1941,999 1971,999
  other v1: 1971,975 1971,1021
NetD9_2: D9.2 R17.1 | length 82.3
  Top Layer w30: D9.2@4279.95,988.23 R17.1@4279.95,1070.5
NetQ1_2: Q1.2 Q1.4 R2.1 | length 324.1
  Top Layer w35: Q1.4@2078,270.57 Q1.2@2078,372.93 2078,449.86 ; R2.1@2078,507 2078,449.86 ; R2.1@2140,511.86 2078,449.86
NetQ2_1: Q2.1 R7.2 | length 298.1
  Bottom Layer w40: R7.2@1546,739.5 1546,869.47 1586,909.47 v1(1586,960) ; v1@1585,946 v1(1585,1007)
NetR10_1: R10.1 R13.2 TP7.1 | length 1542
  Bottom Layer w30: R10.1@1735.5,196 1726,186.5 1726,151 1766,111 1963,111 2267,415 2267,549 2372,654 2498,654 TP7.1@2499,653
  Bottom Layer w40: R13.2@1388,262.5 1388,218 1409,197 R10.1@1734.5,197
OUT: R7.1 U1.5 | length 95.1
  Bottom Layer w40: 1546,581.39 R7.1@1546,676.5
RT/SYNC: R9.2 U1.9 | length 122.9
  Bottom Layer w11: U1.9@1726.6,508.31 1803.69,508.31 1823,489 R9.2@1823,470.5
SS: C12.1 U1.10 | length 70.8
  Bottom Layer w11: U1.10@1726.6,488.63 1747.37,488.63 1752,484 C12.1@1752,440.5
SW_NODE: D2.2 Q2.4 T1.3 T1.4 TP5.1 | length 733.1
  Bottom Layer w30: D2.2@2208,1592.26 2212.26,1588 2311,1588 2402,1679 2402,1991 2447,2036 TP5.1@2571,2036
  other v1: 1431,1222 1482,1222 1535,1222 1588,1222 1640,1222 1695,1222 1754,1222 1804,1222 1430,1285 1481,1285 1534,1285 1587,1285 1639,1285 1694,1285 1753,1285 1803,1285 1429,1342 1480,1342 1533,1342 1586,1342 1638,1342 1693,1342 1752,1342 1802,1342 1429,1401 1480,1401 1533,1401 1586,1401 1638,1401 1693,1401 1752,1401 1802,1401 1431,1463 1482,1463 1535,1463 1588,1463 1640,1463 1695,1463 1754,1463 1804,1463 1427,1526 1478,1526 1531,1526 1584,1526 1636,1526 1691,1526 1750,1526 1800,1526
